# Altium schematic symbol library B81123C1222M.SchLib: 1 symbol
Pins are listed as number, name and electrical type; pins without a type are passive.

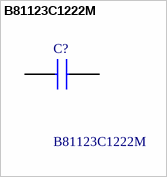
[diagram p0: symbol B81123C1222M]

## B81123C1222M
designator C?
Safety Capacitors 0.0022uF 500Vac 20% Class Y1; Manufacturer_Name: TDK; Geometry.Height: 12.5mm
footprint B81123C1222M
pins: 1, 2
